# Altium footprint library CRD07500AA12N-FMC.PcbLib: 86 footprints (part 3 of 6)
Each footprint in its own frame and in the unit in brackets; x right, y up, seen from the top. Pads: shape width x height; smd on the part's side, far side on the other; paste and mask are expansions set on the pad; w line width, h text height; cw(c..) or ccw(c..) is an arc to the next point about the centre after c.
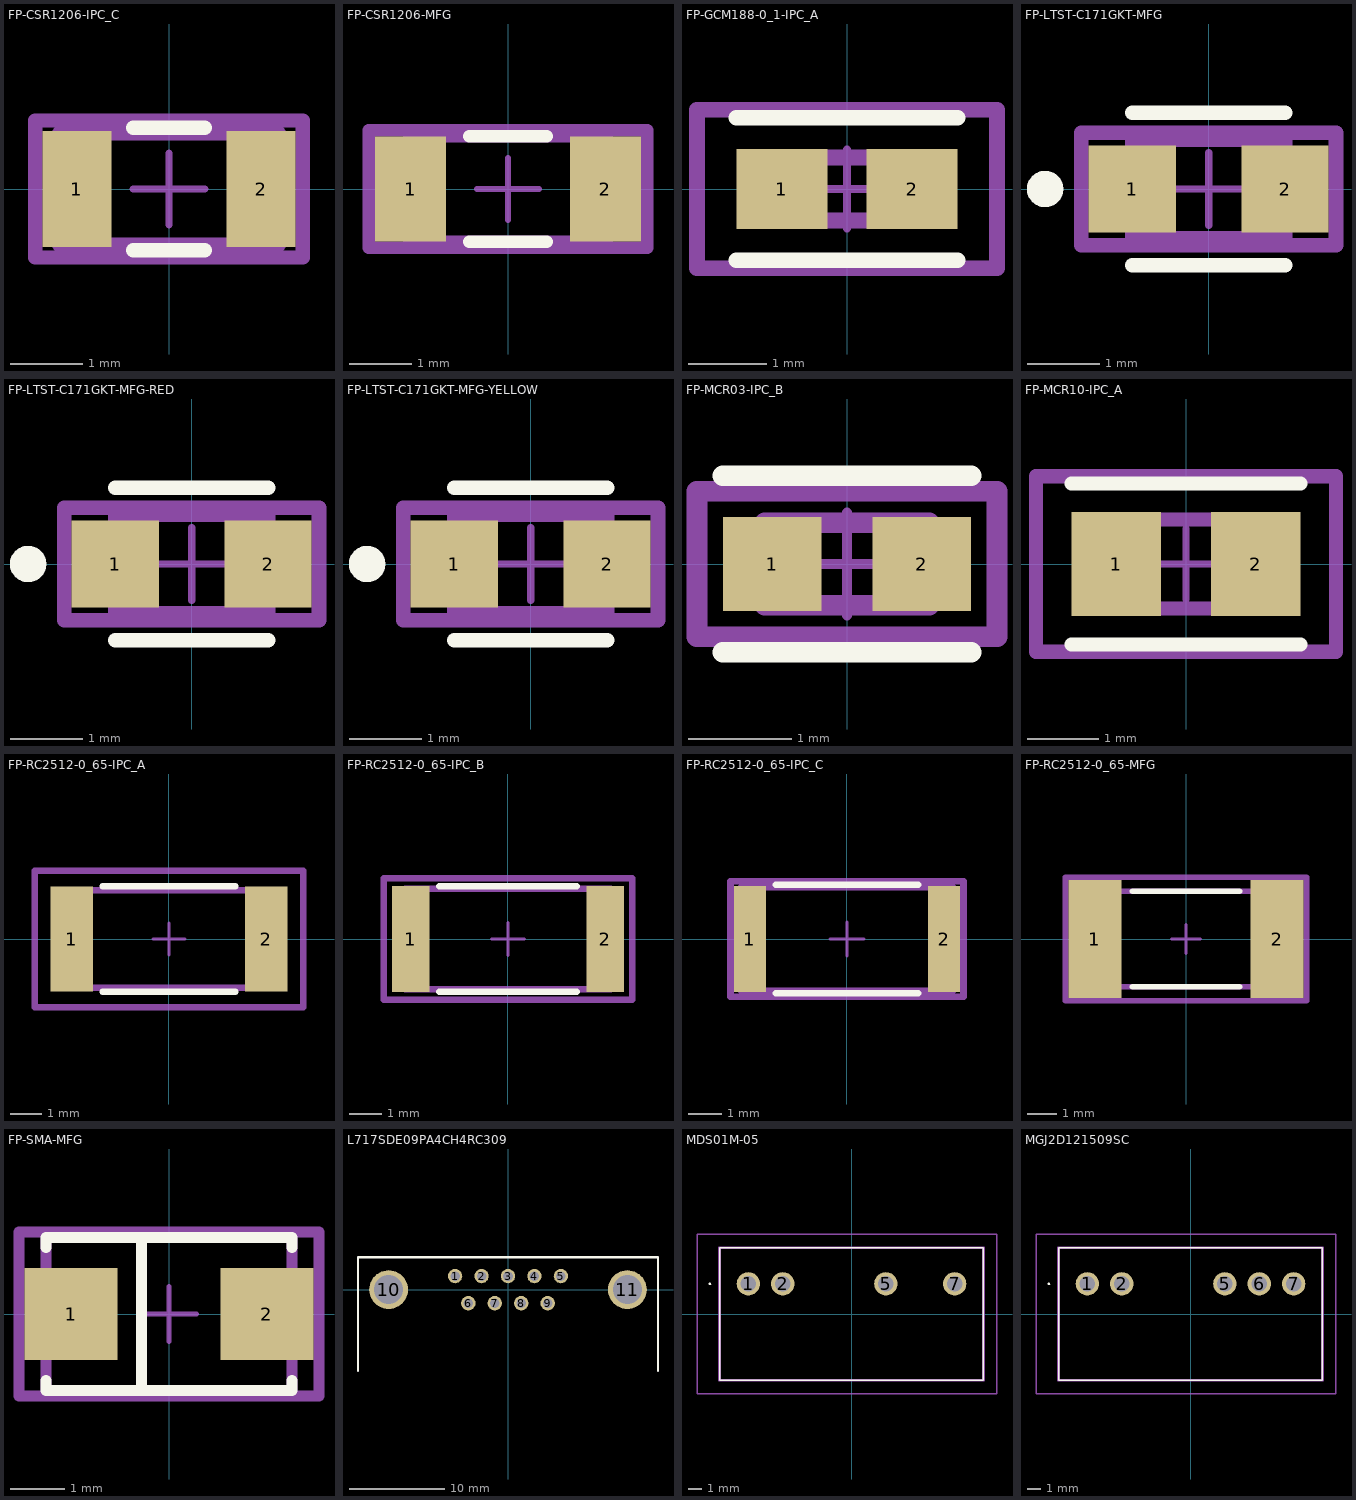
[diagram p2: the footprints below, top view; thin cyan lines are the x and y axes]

## FP-CSR1206-IPC_C [mm]
pads (2):
  rect 0.956x1.608 smd paste+0 mask+0: 1(-1.276,0) 2(1.276,0)
Top Overlay:
  lines w0.2: -0.498,-0.85 0.498,-0.85 ; -0.498,0.85 0.498,0.85
Mechanical 5:
  lines w0.2: -1.854,-0.95 1.854,-0.95 1.854,0.95 -1.854,0.95 -1.854,-0.95
  text ".Designator" at 0,0.188 h1
Mechanical 13:
  lines w0.2: -1.525,-0.775 1.525,-0.775 1.525,0.775 -1.525,0.775 -1.525,-0.775
Mechanical 15:
  lines w0.2: -1.854,-0.95 1.854,-0.95 1.854,0.95 -1.854,0.95 -1.854,-0.95
Mechanical 16:
  lines w0.1: -0.5,0 0.5,0 ; 0,-0.5 0,0.5
3D body "Res_Stackpole_Electronics_CSR1206FKR500_eec.STEP": height 0.25, standoff 0, extent -1.854,-0.95 1.854,0.95

## FP-CSR1206-MFG [mm]
pads (2):
  rect 1.15x1.7 smd paste+0 mask+0: 1(-1.575,0) 2(1.575,0)
Top Overlay:
  lines w0.2: -0.625,-0.85 0.625,-0.85 ; -0.625,0.85 0.625,0.85
Mechanical 5:
  lines w0.2: -2.25,-0.95 -2.25,0.95 2.25,0.95 2.25,-0.95 -2.25,-0.95
  text ".Designator" at 0,0.188 h1
Mechanical 13:
  lines w0.2: -1.6,-0.85 -1.6,0.85 1.6,0.85 1.6,-0.85 -1.6,-0.85
Mechanical 15:
  lines w0.2: -2.25,-0.95 -2.25,0.95 2.25,0.95 2.25,-0.95 -2.25,-0.95
Mechanical 16:
  lines w0.1: -0.5,0 0.5,0 ; 0,-0.5 0,0.5
3D body "Res_Stackpole_Electronics_CSR1206FKR500_eec.STEP": height 0.25, standoff 0, extent -2.25,-0.95 2.25,0.95

## FP-GCM188-0_1-IPC_A [mm]
pads (2):
  rect 1.159x1.012 smd paste+0 mask+0: 1(-0.827,0) 2(0.827,0)
Top Overlay:
  lines w0.2: -1.406,-0.906 1.406,-0.906 ; -1.406,0.906 1.406,0.906
Mechanical 5:
  lines w0.2: -1.906,-1.006 1.906,-1.006 1.906,1.006 -1.906,1.006 -1.906,-1.006
  text ".Designator" at 0,0.188 h1
Mechanical 13:
  lines w0.2: -0.8,-0.4 0.8,-0.4 0.8,0.4 -0.8,0.4 -0.8,-0.4
Mechanical 15:
  lines w0.2: -1.906,-1.006 1.906,-1.006 1.906,1.006 -1.906,1.006 -1.906,-1.006
Mechanical 16:
  lines w0.1: -0.5,0 0.5,0 ; 0,-0.5 0,0.5
3D body "Cap_Murata_GCM1885C2A5R3BA16J_eec.STEP": height 0.25, standoff 0, extent -1.906,-1.006 1.906,1.006

## FP-LTST-C171GKT-MFG [mm]
pads (2):
  rect 1.2x1.2 smd paste+0 mask+0: 1(-1.05,0) 2(1.05,0)
Top Overlay:
  circle w0.25: c-2.25,0 r0.125
  lines w0.2: -1.05,-1.05 1.05,-1.05 ; -1.05,1.05 1.05,1.05
Mechanical 5:
  lines w0.2: -1.75,-0.775 1.75,-0.775 1.75,0.775 -1.75,0.775 -1.75,-0.775
  text ".Designator" at 0,0 h1
Mechanical 13:
  lines w0.2: -1.05,-0.675 1.05,-0.675 1.05,0.675 -1.05,0.675 -1.05,-0.675
Mechanical 15:
  lines w0.2: -1.75,-0.775 1.75,-0.775 1.75,0.775 -1.75,0.775 -1.75,-0.775
Mechanical 16:
  lines w0.1: -0.5,0 0.5,0 ; 0,-0.5 0,0.5
3D body "Diode_Lite-On_LTST-C171GKT_eec.STEP": height 0.25, standoff 0, extent -1.75,-0.775 1.75,0.775

## FP-LTST-C171GKT-MFG-RED [mm]
pads (2):
  rect 1.2x1.2 smd paste+0 mask+0: 1(-1.05,0) 2(1.05,0)
Top Overlay:
  circle w0.25: c-2.25,0 r0.125
  lines w0.2: -1.05,-1.05 1.05,-1.05 ; -1.05,1.05 1.05,1.05
Mechanical 5:
  lines w0.2: -1.75,-0.775 1.75,-0.775 1.75,0.775 -1.75,0.775 -1.75,-0.775
  text ".Designator" at 0,0 h1
Mechanical 13:
  lines w0.2: -1.05,-0.675 1.05,-0.675 1.05,0.675 -1.05,0.675 -1.05,-0.675
Mechanical 15:
  lines w0.2: -1.75,-0.775 1.75,-0.775 1.75,0.775 -1.75,0.775 -1.75,-0.775
Mechanical 16:
  lines w0.1: -0.5,0 0.5,0 ; 0,-0.5 0,0.5
3D body "LED 0805 - RED.STEP": height 0.8, standoff 0, extent -1,-0.625 1,0.625

## FP-LTST-C171GKT-MFG-YELLOW [mm]
pads (2):
  rect 1.2x1.2 smd paste+0 mask+0: 1(-1.05,0) 2(1.05,0)
Top Overlay:
  circle w0.25: c-2.25,0 r0.125
  lines w0.2: -1.05,-1.05 1.05,-1.05 ; -1.05,1.05 1.05,1.05
Mechanical 5:
  lines w0.2: -1.75,-0.775 -1.75,0.775 1.75,0.775 1.75,-0.775 -1.75,-0.775
  text ".Designator" at 0,0 h1
Mechanical 13:
  lines w0.2: -1.05,-0.675 -1.05,0.675 1.05,0.675 1.05,-0.675 -1.05,-0.675
Mechanical 15:
  lines w0.2: -1.75,-0.775 -1.75,0.775 1.75,0.775 1.75,-0.775 -1.75,-0.775
Mechanical 16:
  lines w0.1: -0.5,0 0.5,0 ; 0,-0.5 0,0.5
3D body "LED 0805 - YELLOW.STEP": height 0.8, standoff 0, extent -1,-0.625 1,0.625

## FP-MCR03-IPC_B [mm]
pads (2):
  rect 0.958x0.912 smd paste+0 mask+0: 1(-0.727,0) 2(0.727,0)
Top Overlay:
  lines w0.2: -1.206,-0.856 1.206,-0.856 ; -1.206,0.856 1.206,0.856
Mechanical 5:
  lines w0.2: -1.456,-0.706 1.456,-0.706 1.456,0.706 -1.456,0.706 -1.456,-0.706
  text ".Designator" at 0,0.188 h1
Mechanical 13:
  lines w0.2: -0.8,-0.4 0.8,-0.4 0.8,0.4 -0.8,0.4 -0.8,-0.4
Mechanical 15:
  lines w0.2: -1.456,-0.706 1.456,-0.706 1.456,0.706 -1.456,0.706 -1.456,-0.706
Mechanical 16:
  lines w0.1: -0.5,0 0.5,0 ; 0,-0.5 0,0.5
3D body "Res_Rohm_MCR03ERTF1182_eec.STEP": height 0.25, standoff 0, extent -1.456,-0.706 1.456,0.706

## FP-MCR10-IPC_A [mm]
pads (2):
  rect 1.258x1.462 smd paste+0 mask+0: 1(-0.977,0) 2(0.977,0)
Top Overlay:
  lines w0.2: -1.606,-1.131 1.606,-1.131 ; -1.606,1.131 1.606,1.131
Mechanical 5:
  lines w0.2: -2.106,-1.231 -2.106,1.231 2.106,1.231 2.106,-1.231 -2.106,-1.231
  text ".Designator" at 0,0.188 h1
Mechanical 13:
  lines w0.2: -1,-0.625 -1,0.625 1,0.625 1,-0.625 -1,-0.625
Mechanical 15:
  lines w0.2: -2.106,-1.231 -2.106,1.231 2.106,1.231 2.106,-1.231 -2.106,-1.231
Mechanical 16:
  lines w0.1: -0.5,0 0.5,0 ; 0,-0.5 0,0.5
3D body "Res_Rohm_MCR10ERTJ510_eec.STEP": height 0.25, standoff 0, extent -2.106,-1.231 2.106,1.231

## FP-RC2512-0_65-IPC_A [mm]
pads (2):
  rect 1.358x3.358 smd paste+0 mask+0: 1(-3.102,0) 2(3.102,0)
Top Overlay:
  lines w0.2: -2.123,-1.679 2.123,-1.679 ; -2.123,1.679 2.123,1.679
Mechanical 5:
  lines w0.2: -4.281,-2.179 -4.281,2.179 4.281,2.179 4.281,-2.179 -4.281,-2.179
  text ".Designator" at 0,0.188 h1
Mechanical 13:
  lines w0.2: -3.175,-1.55 -3.175,1.55 3.175,1.55 3.175,-1.55 -3.175,-1.55
Mechanical 15:
  lines w0.2: -4.281,-2.179 -4.281,2.179 4.281,2.179 4.281,-2.179 -4.281,-2.179
Mechanical 16:
  lines w0.1: -0.5,0 0.5,0 ; 0,-0.5 0,0.5
3D body "Res_Yageo_RC2512JK-07360RL_eec.STEP": height 0.25, standoff 0, extent -4.281,-2.179 4.281,2.179

## FP-RC2512-0_65-IPC_B [mm]
pads (2):
  rect 1.158x3.258 smd paste+0 mask+0: 1(-3.002,0) 2(3.002,0)
Top Overlay:
  lines w0.2: -2.123,-1.629 2.123,-1.629 ; -2.123,1.629 2.123,1.629
Mechanical 5:
  lines w0.2: -3.831,-1.879 -3.831,1.879 3.831,1.879 3.831,-1.879 -3.831,-1.879
  text ".Designator" at 0,0.188 h1
Mechanical 13:
  lines w0.2: -3.175,-1.55 -3.175,1.55 3.175,1.55 3.175,-1.55 -3.175,-1.55
Mechanical 15:
  lines w0.2: -3.831,-1.879 -3.831,1.879 3.831,1.879 3.831,-1.879 -3.831,-1.879
Mechanical 16:
  lines w0.1: -0.5,0 0.5,0 ; 0,-0.5 0,0.5
3D body "Res_Yageo_RC2512JK-07360RL_eec.STEP": height 0.25, standoff 0, extent -3.831,-1.879 3.831,1.879

## FP-RC2512-0_65-IPC_C [mm]
pads (2):
  rect 0.958x3.158 smd paste+0 mask+0: 1(-2.902,0) 2(2.902,0)
Top Overlay:
  lines w0.2: -2.123,-1.625 2.123,-1.625 ; -2.123,1.625 2.123,1.625
Mechanical 5:
  lines w0.2: -3.481,-1.725 -3.481,1.725 3.481,1.725 3.481,-1.725 -3.481,-1.725
  text ".Designator" at 0,0.188 h1
Mechanical 13:
  lines w0.2: -3.175,-1.55 -3.175,1.55 3.175,1.55 3.175,-1.55 -3.175,-1.55
Mechanical 15:
  lines w0.2: -3.481,-1.725 -3.481,1.725 3.481,1.725 3.481,-1.725 -3.481,-1.725
Mechanical 16:
  lines w0.1: -0.5,0 0.5,0 ; 0,-0.5 0,0.5
3D body "Res_Yageo_RC2512JK-07360RL_eec.STEP": height 0.25, standoff 0, extent -3.481,-1.725 3.481,1.725

## FP-RC2512-0_65-MFG [mm]
pads (2):
  rect 1.8x4 smd paste+0 mask+0: 1(-3.1,0) 2(3.1,0)
Top Overlay:
  lines w0.2: -1.825,-1.625 1.825,-1.625 ; -1.825,1.625 1.825,1.625
Mechanical 5:
  lines w0.2: -4.1,-2.1 4.1,-2.1 4.1,2.1 -4.1,2.1 -4.1,-2.1
  text ".Designator" at 0,0.188 h1
Mechanical 13:
  lines w0.2: -3.225,-1.625 3.225,-1.625 3.225,1.625 -3.225,1.625 -3.225,-1.625
Mechanical 15:
  lines w0.2: -4.1,-2.1 4.1,-2.1 4.1,2.1 -4.1,2.1 -4.1,-2.1
Mechanical 16:
  lines w0.1: -0.5,0 0.5,0 ; 0,-0.5 0,0.5
3D body "Res_Yageo_RC2512JK-07360RL_eec.STEP": height 0.25, standoff 0, extent -4.1,-2.1 4.1,2.1

## FP-SMA-MFG [mm]
pads (2):
  rect 1.7x1.68 smd paste+0 mask+0: 1(-1.79,0) 2(1.79,0)
Top Overlay:
  lines w0.2: -2.25,-1.215 -2.25,-1.395 2.25,-1.395 2.25,-1.215 ; -2.25,1.215 -2.25,1.395 2.25,1.395 2.25,1.215 ; -0.5,-1.3 -0.5,1.3
Mechanical 5:
  lines w0.2: -2.74,-1.495 2.74,-1.495 2.74,1.495 -2.74,1.495 -2.74,-1.495
  text ".Designator" at 0,0.188 h1
Mechanical 13:
  lines w0.2: -2.25,-1.395 2.25,-1.395 2.25,1.395 -2.25,1.395 -2.25,-1.395
Mechanical 15:
  lines w0.2: -2.74,-1.495 2.74,-1.495 2.74,1.495 -2.74,1.495 -2.74,-1.495
Mechanical 16:
  lines w0.1: -0.5,0 0.5,0 ; 0,-0.5 0,0.5
3D body "Diode_Vishay_SS1H10-M3-61T_eec.STEP": height 0.25, standoff 0, extent -2.74,-1.495 2.74,1.495

## L717SDE09PA4CH4RC309 [mm] "CONN D-SUB PLUG 9POS R/A SLDR"
height 12.55
pads (11):
  round 1.508 hole 1: 1(-5.54,1.42) 2(-2.77,1.42) 3(0,1.42) 4(2.77,1.42) 5(5.54,1.42) 6(-4.155,-1.42) 7(-1.385,-1.42) 8(1.385,-1.42) 9(4.155,-1.42)
  round 4.066 hole 3.05: 10(-12.495,0) 11(12.495,0)
Top Overlay:
  lines w0.254: -15.7,-8.5 -15.7,3.4 15.7,3.4 15.7,-8.5
3D body "Amphenol L717SDE09PA4CH4RC309 Color.STEP": height 12.55, standoff -3.2, extent -15.4,-15.6 15.405,3

## MDS01M-05 [mm]
pads (4):
  round 1.725 hole 1.15: 1(-7.62,2.23) 2(-5.08,2.23) 5(2.54,2.23) 7(7.62,2.23)
Top Overlay:
  lines w0.1: -10.52,2.23 ccw(c-10.47,2.23) -10.42,2.23 ccw(c-10.47,2.23) -10.52,2.23 ; -9.75,-4.9 -9.75,4.9 9.75,4.9 9.75,-4.9 -9.75,-4.9
Top Designator:
  text ".Designator" at 7.283,0.508 h1.52
Mechanical 13:
  lines w0.2: -9.75,-4.9 -9.75,4.9 9.75,4.9 9.75,-4.9 -9.75,-4.9
Mechanical 15:
  lines w0.1: -11.42,-5.9 -11.42,5.9 10.75,5.9 10.75,-5.9 -11.42,-5.9
3D body "MDS01(H-S-1WR2).stp": height 12.5, standoff -4.1, extent -9.75,-4.9 9.75,4.9

## MGJ2D121509SC [mm]
pads (5):
  round 1.725 hole 1.15: 1(-7.62,2.23) 2(-5.08,2.23) 5(2.54,2.23) 6(5.08,2.23) 7(7.62,2.23)
Top Overlay:
  lines w0.1: -10.52,2.23 ccw(c-10.47,2.23) -10.42,2.23 ccw(c-10.47,2.23) -10.52,2.23 ; -9.75,-4.9 -9.75,4.9 9.75,4.9 9.75,-4.9 -9.75,-4.9
Top Designator:
  text ".Designator" at 7.283,0.508 h1.52
Mechanical 13:
  lines w0.2: -9.75,-4.9 -9.75,4.9 9.75,4.9 9.75,-4.9 -9.75,-4.9
Mechanical 15:
  lines w0.1: -11.42,-5.9 -11.42,5.9 10.75,5.9 10.75,-5.9 -11.42,-5.9
3D body "MGJ2D121503SC.stp": height 13.09, standoff -3.51, extent -9.9,-5.09 9.6,4.73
